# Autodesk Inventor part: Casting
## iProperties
Shininess: 77.0
Length Units: 11269
Angle Units: 11279
Time Units: 11290
Mass Units: 11283
Length Display Precision: 3
Angle Display Precision: 2
Created: 2002-02
Part Number: Casting
Document SubType Name: Modeling
Designer: ***
Density: 0.0
Volumn: 0.0
Area: 0.0
PropertySet Name: Model Information
Control State: 0
Master: False
Checked Out: False
Author: ***
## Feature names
1. Extrusion1
2. Extrusion2
3. Extrusion3
4. Extrusion4
5. Extrusion5
6. Mirror1
7. Extrusion6
